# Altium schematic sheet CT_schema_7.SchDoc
size 366 x 245 mm
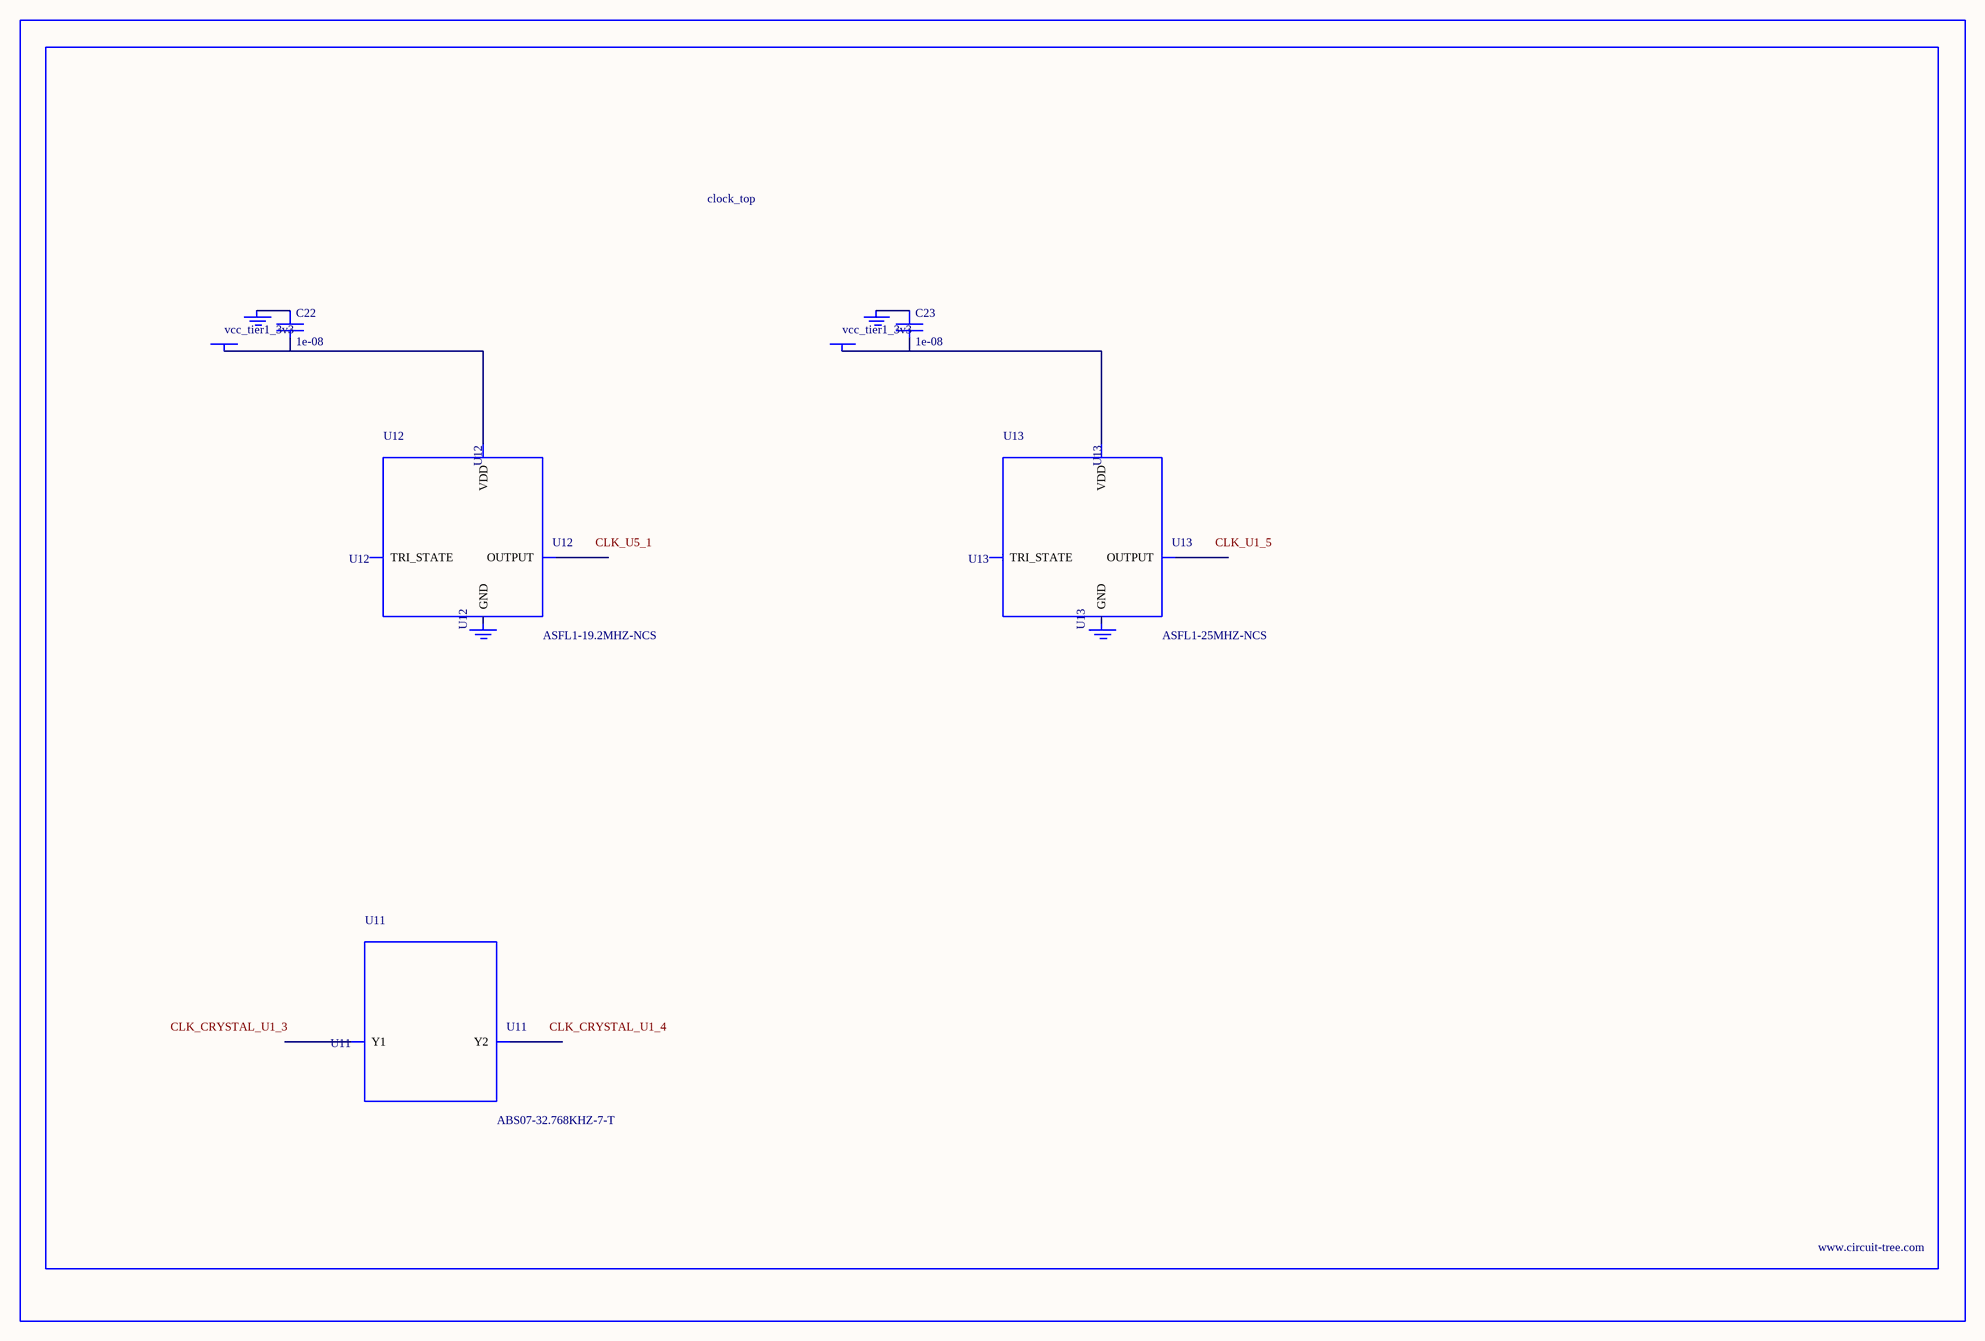
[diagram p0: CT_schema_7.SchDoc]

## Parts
BORDER6  (no value)
C22  1e-08  [C0402]
C23  1e-08  [C0402]
GND_INSTANCE_6_0  (no value)
GND_INSTANCE_6_1  (no value)
GND_INSTANCE_6_2  (no value)
GND_INSTANCE_6_3  (no value)
POWER_INSTANCE_6_0  vcc_tier1_3v3
POWER_INSTANCE_6_1  vcc_tier1_3v3
U11  ABS07-32.768KHZ-7-T  [ABS07-32.768KHZ-7-T]
U12  ASFL1-19.2MHZ-NCS  [ASFL1]
U13  ASFL1-25MHZ-NCS  [ASFL1]

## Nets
NetC22_1: C22.1 GND_INSTANCE_6_0.0(GND)
NetC22_2: C22.2 POWER_INSTANCE_6_0.0(PWR) U12.4(VDD)
NetC23_1: C23.1 GND_INSTANCE_6_2.0(GND)
NetC23_2: C23.2 POWER_INSTANCE_6_1.0(PWR) U13.4(VDD)

Not connected (* = marked no-connect by the designer): GND_INSTANCE_6_1 0(GND); GND_INSTANCE_6_3 0(GND); U11 1(Y1) 2(Y2); U12 1(TRI_STATE) 2(GND) 3(OUTPUT); U13 1(TRI_STATE) 2(GND) 3(OUTPUT)

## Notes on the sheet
- Labels drawn without touching a wire or pin: CLK_CRYSTAL_U1_3, CLK_CRYSTAL_U1_4, CLK_U1_5, CLK_U5_1

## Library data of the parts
BORDER6 = BORDER_PAGE6
C22 C23 = C0402C103K3RAC
GND_INSTANCE_6_0-GND_INSTANCE_6_3 = GND
POWER_INSTANCE_6_0 POWER_INSTANCE_6_1 = PWR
